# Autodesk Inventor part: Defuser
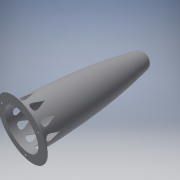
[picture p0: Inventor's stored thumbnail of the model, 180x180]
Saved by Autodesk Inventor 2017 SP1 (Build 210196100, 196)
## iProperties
Created: 2016-12
Part Number: Defuser
Material: Generic
Document SubType Name: Modeling
Designer: HP_ELITE
Density: 1 g/cm^3
Appearance: Default
Author: HP_ELITE
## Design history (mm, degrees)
sketch "Sketch1"
  geometry: L1 (-38.5, 0)-(-38.5, -0.85); L2 (-38.5, -0.85)-(-27, -0.85); L3 (0, 0)-(0, -19.912); L4 (-38.5, 0)-(-27, 0); L5 (-27, 0)-(-27, 35); L6 (-26.35, 35)-(-26.35, -0.4); L7 (-26.35, -0.4)-(-26.35, -0.85); L8 (-26.35, -0.85)-(-27, -0.85); L9 (-14.209, 180.993)-(-13.569, 180.88); L10 (-14.209, 180.993)-(-10.432, 202.382); A1 r 839.573 centre (812.573, 35) between (-14.209, 180.993) and (-27, 35); A2 r 838.923 centre (812.573, 35) between (-13.569, 180.88) and (-26.35, 35)
  constraints: 20 end point, 4 point on circle, 4 vertical, 2 centre point, 2 horizontal, 2 tangent, 1 horizontal alignment, 1 perpendicular, 1 vertical alignment, 1 other
  dimensions: "d0" = 0.85 distance of L1.start L1.end; "d1" = 38.5 distance between parallel lines of L1 L3; "d2" = 11.5 distance of L1.end L2.end; "d3" = 35 distance of L4.end L5.end; "d4" = 839.573 radius of A1; "d5" = 180.993 distance from line of L4 L9.start; "d6" = 0.65 radial gap between concentric circles of A1 A2
revolve "Revolution1" sketch "Sketch1" stored, may be unused: angle "d8" = 90 deg
sketch "Sketch2"
  geometry: C1 r 1.75 at (-28.579, 16.5) reference; C2 r 1.75 at (28.579, 16.5) reference; C3 r 1.75 at (0, -33) reference; 1 further point
extrude "Extrusion1" cut sketch "Sketch2" distance "d9" = 10; taper "d10" = 0 deg
sketch "Sketch3"
  geometry: L1 (24.325, 0)-(37.596, 0); L2 (7.918, 0)-(7.918, -0.657); L3 (7.918, 2.067)-(7.918, -2.067); L4 (7.918, -2.067)-(7.918, 2.067); A1 r 14.08 centre (21.998, 0) between (8.014, 1.642) and (8.014, -1.642); A2 r 14.08 centre (21.998, 0) between (8.014, 1.642) and (8.014, -1.642); 1 further point
  constraints: 8 end point, 4 symmetric about line, 3 horizontal, 3 midpoint, 2 centre point, 2 point on circle, 1 collinear, 1 point on line, 1 vertical, 7 other
extrude "Extrusion2" cut sketch "Sketch3" stored distance "d11" = 10; taper "d12" = 0 deg
pattern_circular "Circular Pattern1" dims angle "d14" = 360 deg
body "Solid1"
node "Reference1"
node "Reference2"
node "Reference3"
